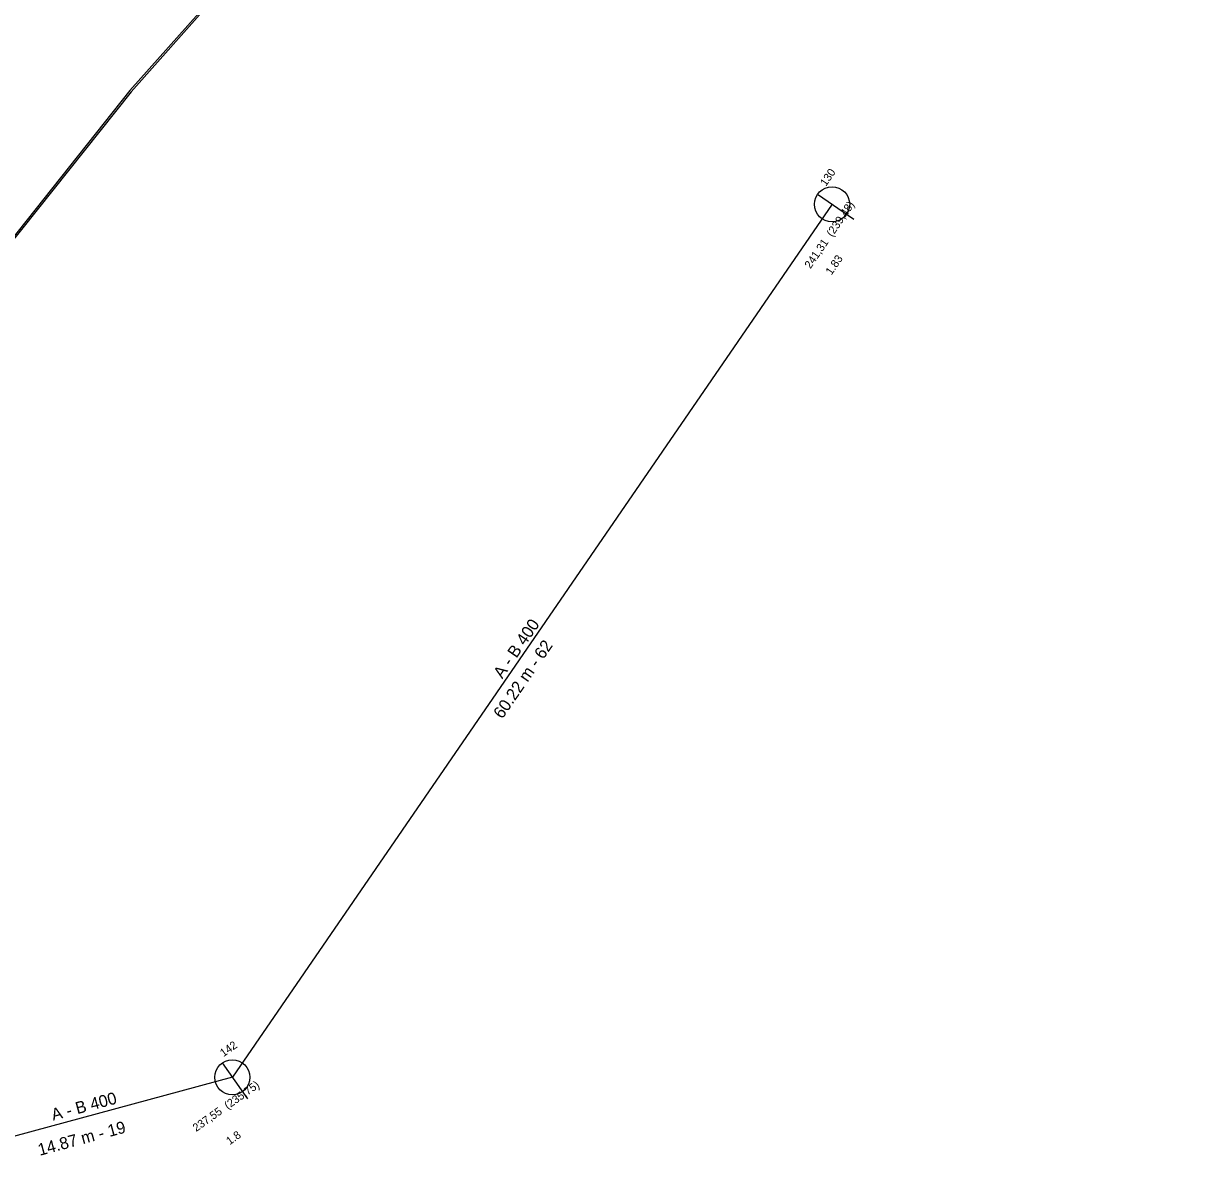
# Model space of a CAD drawing. Extents: x -600636 to -600185, y -1203957 to -1203572.
# Drawn here: x -600368.7 to -600302, y -1203928.6 to -1203864.2 of the extents above; entities that cross this region are included whole.
import ezdxf

# ---------------------------------------------------------------- set-up
doc = ezdxf.new("R2010")
doc.units = 0
for name, color, linetype in [('Default', 7, 'Continuous'), ('popisy_sachta_v_majetku_nebo_provozovana', 7, 'Continuous'), ('popisy_stoka', 7, 'Continuous'), ('sachta_v_majetku_nebo_provozovana', 7, 'Continuous'), ('stoka_v_majetku', 7, 'Continuous')]:
    doc.layers.add(name, color=color, linetype=linetype)

# ---------------------------------------------------------------- blocks, each defined once
blk = doc.blocks.new('MoSymbol 2')
at = {"layer": 'Default'}
blk.add_line((0, 0.00005), (0, -0.000075), dxfattribs=at)
blk.add_circle((0, 0), 0.00005, dxfattribs=at)

msp = doc.modelspace()

# ---------------------------------------------------------------- linework, layer by layer
at = {"layer": 'stoka_v_majetku'}
for p, q in [((-600322.72, -1203874.5), (-600356.82, -1203924.14)), ((-600356.82, -1203924.14), (-600371.18, -1203928.02))]:
    msp.add_line(p, q, dxfattribs=at)
for points in [[(-600301.999, -1203816.723), (-600302.601, -1203817.564), (-600309.957, -1203822.001), (-600326.016, -1203831.688), (-600331.317, -1203836.686), (-600343.362, -1203848.044), (-600352.098, -1203856.282), (-600362.567, -1203868.11), (-600368.81, -1203875.94), (-600393.327, -1203906.691), (-600394.486, -1203908.145)], [(-600301.999, -1203816.723), (-600302.021, -1203816.732), (-600302.61, -1203817.545), (-600326.032, -1203831.648), (-600352.131, -1203856.227), (-600362.652, -1203868.025), (-600394.483, -1203908.108), (-600394.486, -1203908.145)]]:
    msp.add_lwpolyline(points, dxfattribs=at)

# ---------------------------------------------------------------- block references
at = {"layer": 'sachta_v_majetku_nebo_provozovana'}
for p, xscale, yscale, rotation in [((-600322.72, -1203874.5), 19997.500312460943, 19997.50031246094, 55.51303630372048), ((-600356.82, -1203924.14), 19997.50031246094, 19997.500312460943, 35.31651185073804)]:
    msp.add_blockref('MoSymbol 2', p, dxfattribs=dict(at, xscale=xscale, yscale=yscale, rotation=rotation))

# ---------------------------------------------------------------- texts
at = {"layer": 'popisy_sachta_v_majetku_nebo_provozovana'}
for s, height, rotation, p in [('130', 0.4549, 55.51304, (-600323.07, -1203873.509)), ('241,31  (239,48)', 0.45494, 55.51304, (-600323.952, -1203878.197)), ('1.83', 0.4549, 55.51304, (-600322.756, -1203878.556)), ('142', 0.4549, 35.31651, (-600357.324, -1203922.997)), ('237,55  (235,75)', 0.45494, 35.31651, (-600358.873, -1203927.252)), ('1.8', 0.4549, 35.31651, (-600356.972, -1203928.006))]:
    msp.add_text(s, height=height, rotation=rotation, dxfattribs=at).set_placement(p)
at = {"layer": 'popisy_stoka'}
for s, height, rotation, p in [('A - B 400', 0.6824, 55.51304, (-600341.472, -1203901.515)), ('60.22 m - 62', 0.68241, 55.51304, (-600341.471, -1203903.801)), ('A - B 400', 0.6824, 15.11999, (-600367.007, -1203926.61)), ('14.87 m - 19', 0.68241, 15.11999, (-600367.77, -1203928.605))]:
    msp.add_text(s, height=height, rotation=rotation, dxfattribs=at).set_placement(p)

doc.saveas('drawing.dxf')
